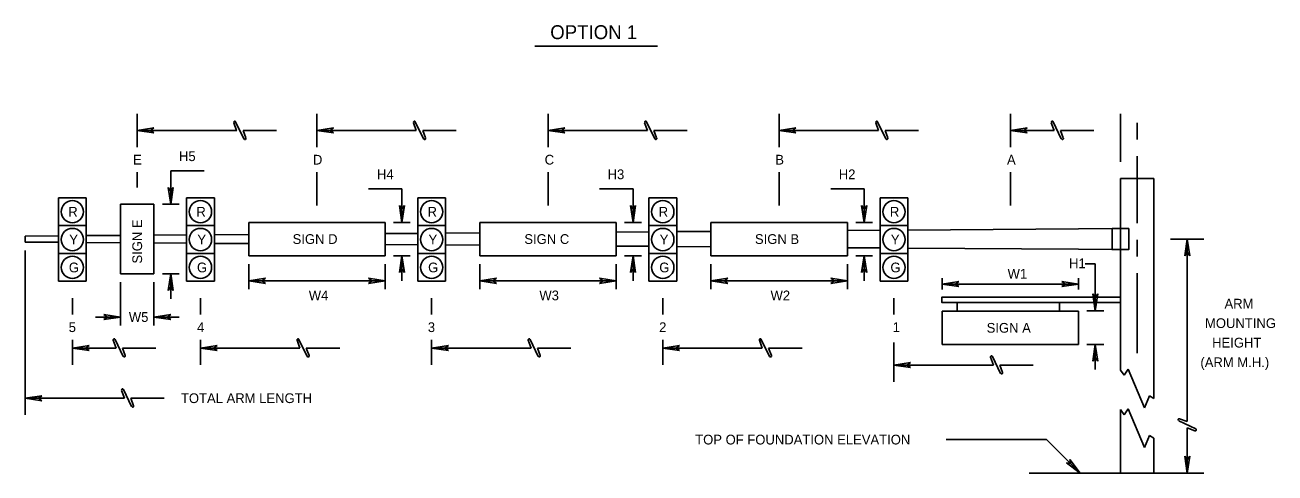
# Model space of a CAD drawing. Extents: x 2146427 to 2147986, y 2147023 to 2147568.
# Drawn here: x 2146426.5 to 2146875.4, y 2147407.4 to 2147568.2 of the extents above; entities that cross this region are included whole.
import ezdxf

# ---------------------------------------------------------------- set-up
doc = ezdxf.new("R2010")
doc.units = 0
doc.layers.add('50', color=7, linetype='Continuous')

msp = doc.modelspace()

# ---------------------------------------------------------------- linework, layer by layer
at = {"layer": '50'}
for p, q in [((2146609.58, 2147560.7), (2146653.58, 2147560.7)), ((2146466.84, 2147524.36), (2146466.84, 2147536.37)), ((2146531.34, 2147524.36), (2146531.34, 2147536.37)), ((2146614.34, 2147524.36), (2146614.34, 2147536.37)), ((2146697.34, 2147524.36), (2146697.34, 2147536.37)), ((2146780.34, 2147524.36), (2146780.34, 2147536.37)), ((2146819.84, 2147519.12), (2146819.84, 2147536.37)), ((2146472.84, 2147531.26), (2146466.84, 2147530.36)), ((2146471.64, 2147530.36), (2146472.84, 2147531.26)), ((2146502.52, 2147530.37), (2146501.52, 2147533.17)), ((2146505.12, 2147527.37), (2146502.17, 2147533.47)), ((2146537.34, 2147531.26), (2146531.34, 2147530.36)), ((2146536.14, 2147530.36), (2146537.34, 2147531.26)), ((2146567.02, 2147530.37), (2146566.02, 2147533.17)), ((2146569.62, 2147527.37), (2146566.67, 2147533.47)), ((2146620.34, 2147531.26), (2146614.34, 2147530.36)), ((2146619.14, 2147530.36), (2146620.34, 2147531.26)), ((2146650.02, 2147530.37), (2146649.02, 2147533.17)), ((2146652.62, 2147527.37), (2146649.67, 2147533.47)), ((2146703.34, 2147531.26), (2146697.34, 2147530.36)), ((2146702.14, 2147530.36), (2146703.34, 2147531.26)), ((2146733.02, 2147530.37), (2146732.02, 2147533.17)), ((2146735.62, 2147527.37), (2146732.67, 2147533.47)), ((2146786.34, 2147531.26), (2146780.34, 2147530.36)), ((2146785.14, 2147530.36), (2146786.34, 2147531.26)), ((2146796.02, 2147530.37), (2146795.02, 2147533.17)), ((2146798.62, 2147527.37), (2146795.67, 2147533.47)), ((2146825.84, 2147527.12), (2146825.84, 2147533.12)), ((2146466.84, 2147530.36), (2146502.54, 2147530.36)), ((2146466.84, 2147530.36), (2146472.84, 2147529.46)), ((2146472.84, 2147529.46), (2146471.64, 2147530.36)), ((2146505.82, 2147527.67), (2146504.82, 2147530.37)), ((2146504.84, 2147530.36), (2146516.84, 2147530.36)), ((2146531.34, 2147530.36), (2146567.04, 2147530.36)), ((2146531.34, 2147530.36), (2146537.34, 2147529.46)), ((2146537.34, 2147529.46), (2146536.14, 2147530.36)), ((2146570.32, 2147527.67), (2146569.32, 2147530.37)), ((2146569.34, 2147530.36), (2146581.34, 2147530.36)), ((2146614.34, 2147530.36), (2146650.04, 2147530.36)), ((2146614.34, 2147530.36), (2146620.34, 2147529.46)), ((2146620.34, 2147529.46), (2146619.14, 2147530.36)), ((2146653.32, 2147527.67), (2146652.32, 2147530.37)), ((2146652.34, 2147530.36), (2146664.34, 2147530.36)), ((2146697.34, 2147530.36), (2146733.04, 2147530.36)), ((2146697.34, 2147530.36), (2146703.34, 2147529.46)), ((2146703.34, 2147529.46), (2146702.14, 2147530.36)), ((2146736.32, 2147527.67), (2146735.32, 2147530.37)), ((2146735.34, 2147530.36), (2146747.34, 2147530.36)), ((2146780.34, 2147530.36), (2146786.34, 2147529.46)), ((2146780.34, 2147530.36), (2146796.04, 2147530.36)), ((2146786.34, 2147529.46), (2146785.14, 2147530.36)), ((2146799.32, 2147527.67), (2146798.32, 2147530.37)), ((2146798.34, 2147530.36), (2146810.34, 2147530.36)), ((2146825.84, 2147521.12), (2146825.84, 2147497.12)), ((2146466.84, 2147509.87), (2146466.84, 2147515.36)), ((2146478.84, 2147503.87), (2146478.84, 2147515.87)), ((2146478.84, 2147515.87), (2146490.84, 2147515.87)), ((2146531.34, 2147503.37), (2146531.34, 2147515.36)), ((2146614.34, 2147503.37), (2146614.34, 2147515.36)), ((2146697.34, 2147503.37), (2146697.34, 2147515.36)), ((2146780.34, 2147503.37), (2146780.34, 2147515.36)), ((2146478.84, 2147508.67), (2146477.94, 2147509.87)), ((2146477.94, 2147509.87), (2146478.84, 2147503.87)), ((2146478.84, 2147503.87), (2146479.74, 2147509.87)), ((2146479.74, 2147509.87), (2146478.84, 2147508.67)), ((2146561.84, 2147509.37), (2146549.84, 2147509.37)), ((2146561.84, 2147497.37), (2146561.84, 2147509.37)), ((2146644.84, 2147509.37), (2146632.84, 2147509.37)), ((2146644.84, 2147497.37), (2146644.84, 2147509.37)), ((2146727.84, 2147509.37), (2146715.84, 2147509.37)), ((2146727.84, 2147497.37), (2146727.84, 2147509.37)), ((2146819.84, 2147513.12), (2146831.84, 2147513.12)), ((2146819.84, 2147513.12), (2146819.84, 2147444.34)), ((2146831.84, 2147513.12), (2146831.84, 2147434.14)), ((2146448.53, 2147506.2), (2146438.53, 2147506.2)), ((2146438.53, 2147506.2), (2146438.53, 2147476.2)), ((2146448.53, 2147506.2), (2146448.53, 2147476.2)), ((2146494.53, 2147506.2), (2146484.53, 2147506.2)), ((2146484.53, 2147506.2), (2146484.53, 2147476.2)), ((2146494.53, 2147506.2), (2146494.53, 2147476.2)), ((2146577.53, 2147506.2), (2146567.53, 2147506.2)), ((2146567.53, 2147506.2), (2146567.53, 2147476.2)), ((2146577.53, 2147506.2), (2146577.53, 2147476.2)), ((2146660.53, 2147506.2), (2146650.53, 2147506.2)), ((2146650.53, 2147506.2), (2146650.53, 2147476.2)), ((2146660.53, 2147506.2), (2146660.53, 2147476.2)), ((2146743.53, 2147506.2), (2146733.53, 2147506.2)), ((2146733.53, 2147506.2), (2146733.53, 2147476.2)), ((2146743.53, 2147506.2), (2146743.53, 2147476.2)), ((2146460.84, 2147503.87), (2146460.84, 2147478.87)), ((2146460.84, 2147503.87), (2146472.84, 2147503.87)), ((2146472.84, 2147503.87), (2146472.84, 2147478.87)), ((2146475.84, 2147503.87), (2146481.84, 2147503.87)), ((2146561.84, 2147502.17), (2146560.94, 2147503.37)), ((2146560.94, 2147503.37), (2146561.84, 2147497.37)), ((2146561.84, 2147497.37), (2146562.74, 2147503.37)), ((2146562.74, 2147503.37), (2146561.84, 2147502.17)), ((2146644.84, 2147502.17), (2146643.94, 2147503.37)), ((2146643.94, 2147503.37), (2146644.84, 2147497.37)), ((2146644.84, 2147497.37), (2146645.74, 2147503.37)), ((2146645.74, 2147503.37), (2146644.84, 2147502.17)), ((2146727.84, 2147502.17), (2146726.94, 2147503.37)), ((2146726.94, 2147503.37), (2146727.84, 2147497.37)), ((2146727.84, 2147497.37), (2146728.74, 2147503.37)), ((2146728.74, 2147503.37), (2146727.84, 2147502.17)), ((2146448.53, 2147496.2), (2146438.53, 2147496.2)), ((2146494.53, 2147496.2), (2146484.53, 2147496.2)), ((2146506.84, 2147497.37), (2146555.84, 2147497.37)), ((2146506.84, 2147497.37), (2146506.84, 2147485.37)), ((2146555.84, 2147497.37), (2146555.84, 2147485.37)), ((2146558.84, 2147497.37), (2146564.84, 2147497.37)), ((2146577.53, 2147496.2), (2146567.53, 2147496.2)), ((2146589.84, 2147497.37), (2146638.84, 2147497.37)), ((2146589.84, 2147497.37), (2146589.84, 2147485.37)), ((2146638.84, 2147497.37), (2146638.84, 2147485.37)), ((2146641.84, 2147497.37), (2146647.84, 2147497.37)), ((2146660.53, 2147496.2), (2146650.53, 2147496.2)), ((2146672.84, 2147497.37), (2146721.84, 2147497.37)), ((2146672.84, 2147497.37), (2146672.84, 2147485.37)), ((2146721.84, 2147497.37), (2146721.84, 2147485.37)), ((2146724.84, 2147497.37), (2146730.84, 2147497.37)), ((2146743.53, 2147496.2), (2146733.53, 2147496.2)), ((2146438.53, 2147492.54), (2146426.53, 2147492.45)), ((2146426.53, 2147490.28), (2146426.53, 2147492.45)), ((2146460.84, 2147492.69), (2146448.53, 2147492.61)), ((2146484.53, 2147492.85), (2146472.84, 2147492.77)), ((2146506.84, 2147493), (2146494.53, 2147492.92)), ((2146567.53, 2147493.42), (2146555.84, 2147493.34)), ((2146589.84, 2147493.57), (2146577.53, 2147493.49)), ((2146650.53, 2147493.98), (2146638.84, 2147493.9)), ((2146672.84, 2147494.14), (2146660.53, 2147494.05)), ((2146733.53, 2147494.55), (2146721.84, 2147494.47)), ((2146804.84, 2147495.04), (2146743.53, 2147494.62)), ((2146816.84, 2147495.12), (2146804.84, 2147495.04)), ((2146825.84, 2147485.12), (2146825.84, 2147491.12)), ((2146837.84, 2147491.37), (2146849.84, 2147491.37)), ((2146843.84, 2147491.37), (2146842.94, 2147485.37)), ((2146844.74, 2147485.37), (2146843.84, 2147491.37)), ((2146843.84, 2147491.37), (2146843.84, 2147425.85)), ((2146438.53, 2147490.2), (2146426.53, 2147490.28)), ((2146426.53, 2147487.28), (2146426.53, 2147428.2)), ((2146460.84, 2147490.05), (2146448.53, 2147490.13)), ((2146484.53, 2147489.89), (2146472.84, 2147489.97)), ((2146506.84, 2147489.74), (2146494.53, 2147489.82)), ((2146567.53, 2147489.32), (2146555.84, 2147489.4)), ((2146589.84, 2147489.17), (2146577.53, 2147489.25)), ((2146650.53, 2147488.76), (2146638.84, 2147488.83)), ((2146672.84, 2147488.6), (2146660.53, 2147488.69)), ((2146733.53, 2147488.19), (2146721.84, 2147488.27)), ((2146804.84, 2147487.7), (2146743.53, 2147488.12)), ((2146816.84, 2147487.62), (2146804.84, 2147487.7)), ((2146842.94, 2147485.37), (2146843.84, 2147486.57)), ((2146843.84, 2147486.57), (2146844.74, 2147485.37)), ((2146448.53, 2147486.2), (2146438.53, 2147486.2)), ((2146494.53, 2147486.2), (2146484.53, 2147486.2)), ((2146506.84, 2147485.37), (2146555.84, 2147485.37)), ((2146506.84, 2147482.37), (2146506.84, 2147473.36)), ((2146555.84, 2147482.37), (2146555.84, 2147473.36)), ((2146558.84, 2147485.37), (2146564.84, 2147485.37)), ((2146561.84, 2147485.37), (2146560.94, 2147479.37)), ((2146561.84, 2147485.37), (2146561.84, 2147476.37)), ((2146562.74, 2147479.37), (2146561.84, 2147485.37)), ((2146577.53, 2147486.2), (2146567.53, 2147486.2)), ((2146589.84, 2147485.37), (2146638.84, 2147485.37)), ((2146589.84, 2147482.37), (2146589.84, 2147473.36)), ((2146638.84, 2147482.37), (2146638.84, 2147473.36)), ((2146641.84, 2147485.37), (2146647.84, 2147485.37)), ((2146644.84, 2147485.37), (2146643.94, 2147479.37)), ((2146644.84, 2147485.37), (2146644.84, 2147476.37)), ((2146645.74, 2147479.37), (2146644.84, 2147485.37)), ((2146660.53, 2147486.2), (2146650.53, 2147486.2)), ((2146672.84, 2147485.37), (2146721.84, 2147485.37)), ((2146672.84, 2147482.37), (2146672.84, 2147473.36)), ((2146721.84, 2147482.37), (2146721.84, 2147473.36)), ((2146724.84, 2147485.37), (2146730.84, 2147485.37)), ((2146727.84, 2147485.37), (2146726.94, 2147479.37)), ((2146727.84, 2147485.37), (2146727.84, 2147476.37)), ((2146728.74, 2147479.37), (2146727.84, 2147485.37)), ((2146743.53, 2147486.2), (2146733.53, 2147486.2)), ((2146810.84, 2147482.46), (2146807.21, 2147482.46)), ((2146810.84, 2147465.65), (2146810.84, 2147482.46)), ((2146460.84, 2147478.87), (2146472.84, 2147478.87)), ((2146475.84, 2147478.87), (2146481.84, 2147478.87)), ((2146478.84, 2147478.87), (2146477.94, 2147472.87)), ((2146478.84, 2147478.87), (2146478.84, 2147469.87)), ((2146479.74, 2147472.87), (2146478.84, 2147478.87)), ((2146560.94, 2147479.37), (2146561.84, 2147480.57)), ((2146561.84, 2147480.57), (2146562.74, 2147479.37)), ((2146643.94, 2147479.37), (2146644.84, 2147480.57)), ((2146644.84, 2147480.57), (2146645.74, 2147479.37)), ((2146726.94, 2147479.37), (2146727.84, 2147480.57)), ((2146727.84, 2147480.57), (2146728.74, 2147479.37)), ((2146825.84, 2147479.12), (2146825.84, 2147450.34)), ((2146438.53, 2147476.2), (2146448.53, 2147476.2)), ((2146460.84, 2147475.87), (2146460.84, 2147460.36)), ((2146472.84, 2147475.87), (2146472.84, 2147460.36)), ((2146477.94, 2147472.87), (2146478.84, 2147474.07)), ((2146478.84, 2147474.07), (2146479.74, 2147472.87)), ((2146484.53, 2147476.2), (2146494.53, 2147476.2)), ((2146506.84, 2147476.37), (2146512.84, 2147477.27)), ((2146506.84, 2147476.37), (2146555.84, 2147476.37)), ((2146512.84, 2147475.47), (2146506.84, 2147476.37)), ((2146512.84, 2147477.27), (2146511.64, 2147476.37)), ((2146511.64, 2147476.37), (2146512.84, 2147475.47)), ((2146555.84, 2147476.37), (2146549.84, 2147477.27)), ((2146549.84, 2147477.27), (2146551.04, 2147476.37)), ((2146551.04, 2147476.37), (2146549.84, 2147475.47)), ((2146549.84, 2147475.47), (2146555.84, 2147476.37)), ((2146567.53, 2147476.2), (2146577.53, 2147476.2)), ((2146589.84, 2147476.37), (2146595.84, 2147477.27)), ((2146589.84, 2147476.37), (2146638.84, 2147476.37)), ((2146595.84, 2147475.47), (2146589.84, 2147476.37)), ((2146595.84, 2147477.27), (2146594.64, 2147476.37)), ((2146594.64, 2147476.37), (2146595.84, 2147475.47)), ((2146638.84, 2147476.37), (2146632.84, 2147477.27)), ((2146632.84, 2147477.27), (2146634.04, 2147476.37)), ((2146634.04, 2147476.37), (2146632.84, 2147475.47)), ((2146632.84, 2147475.47), (2146638.84, 2147476.37)), ((2146650.53, 2147476.2), (2146660.53, 2147476.2)), ((2146672.84, 2147476.37), (2146678.84, 2147477.27)), ((2146672.84, 2147476.37), (2146721.84, 2147476.37)), ((2146678.84, 2147475.47), (2146672.84, 2147476.37)), ((2146678.84, 2147477.27), (2146677.64, 2147476.37)), ((2146677.64, 2147476.37), (2146678.84, 2147475.47)), ((2146721.84, 2147476.37), (2146715.84, 2147477.27)), ((2146715.84, 2147477.27), (2146717.04, 2147476.37)), ((2146717.04, 2147476.37), (2146715.84, 2147475.47)), ((2146715.84, 2147475.47), (2146721.84, 2147476.37)), ((2146733.53, 2147476.2), (2146743.53, 2147476.2)), ((2146755.84, 2147477.37), (2146755.84, 2147473.24)), ((2146755.84, 2147475.18), (2146761.84, 2147476.08)), ((2146755.84, 2147475.18), (2146804.84, 2147475.18)), ((2146761.84, 2147474.28), (2146755.84, 2147475.18)), ((2146761.84, 2147476.08), (2146760.64, 2147475.18)), ((2146760.64, 2147475.18), (2146761.84, 2147474.28)), ((2146804.84, 2147475.18), (2146798.84, 2147476.08)), ((2146798.84, 2147476.08), (2146800.04, 2147475.18)), ((2146800.04, 2147475.18), (2146798.84, 2147474.28)), ((2146798.84, 2147474.28), (2146804.84, 2147475.18)), ((2146804.84, 2147477.37), (2146804.84, 2147473.24)), ((2146443.53, 2147470.2), (2146443.53, 2147464.22)), ((2146489.53, 2147470.2), (2146489.53, 2147464.22)), ((2146572.53, 2147470.2), (2146572.53, 2147464.22)), ((2146655.53, 2147470.2), (2146655.53, 2147464.22)), ((2146738.53, 2147470.2), (2146738.53, 2147464.22)), ((2146761.24, 2147468.62), (2146761.24, 2147465.5)), ((2146798.01, 2147468.62), (2146798.01, 2147465.5)), ((2146810.84, 2147470.45), (2146809.94, 2147471.65)), ((2146809.94, 2147471.65), (2146810.84, 2147465.65)), ((2146810.84, 2147465.65), (2146811.74, 2147471.65)), ((2146811.74, 2147471.65), (2146810.84, 2147470.45)), ((2146460.84, 2147463.37), (2146454.84, 2147464.27)), ((2146454.84, 2147464.27), (2146456.04, 2147463.37)), ((2146472.84, 2147463.37), (2146478.84, 2147464.27)), ((2146478.84, 2147464.27), (2146477.64, 2147463.37)), ((2146755.84, 2147465.5), (2146804.84, 2147465.5)), ((2146755.84, 2147465.5), (2146755.84, 2147453.5)), ((2146804.84, 2147465.5), (2146804.84, 2147453.5)), ((2146807.84, 2147465.65), (2146813.84, 2147465.65)), ((2146451.84, 2147463.37), (2146460.84, 2147463.37)), ((2146456.04, 2147463.37), (2146454.84, 2147462.47)), ((2146454.84, 2147462.47), (2146460.84, 2147463.37)), ((2146478.84, 2147462.47), (2146472.84, 2147463.37)), ((2146481.84, 2147463.37), (2146472.84, 2147463.37)), ((2146477.64, 2147463.37), (2146478.84, 2147462.47)), ((2146443.53, 2147455.22), (2146443.53, 2147446.2)), ((2146459.22, 2147452.22), (2146458.22, 2147455.02)), ((2146461.82, 2147449.22), (2146458.87, 2147455.32)), ((2146489.53, 2147455.22), (2146489.53, 2147446.2)), ((2146525.22, 2147452.22), (2146524.22, 2147455.02)), ((2146527.82, 2147449.22), (2146524.87, 2147455.32)), ((2146572.53, 2147455.22), (2146572.53, 2147446.2)), ((2146608.22, 2147452.22), (2146607.22, 2147455.02)), ((2146610.82, 2147449.22), (2146607.87, 2147455.32)), ((2146655.53, 2147455.22), (2146655.53, 2147446.2)), ((2146691.22, 2147452.22), (2146690.22, 2147455.02)), ((2146693.82, 2147449.22), (2146690.87, 2147455.32)), ((2146443.53, 2147452.22), (2146449.53, 2147453.12)), ((2146443.53, 2147452.22), (2146459.23, 2147452.22)), ((2146449.53, 2147451.32), (2146443.53, 2147452.22)), ((2146449.53, 2147453.12), (2146448.33, 2147452.22)), ((2146448.33, 2147452.22), (2146449.53, 2147451.32)), ((2146462.52, 2147449.52), (2146461.52, 2147452.22)), ((2146461.53, 2147452.22), (2146473.53, 2147452.22)), ((2146489.53, 2147452.22), (2146495.53, 2147453.12)), ((2146489.53, 2147452.22), (2146525.23, 2147452.22)), ((2146495.53, 2147451.32), (2146489.53, 2147452.22)), ((2146495.53, 2147453.12), (2146494.33, 2147452.22)), ((2146494.33, 2147452.22), (2146495.53, 2147451.32)), ((2146528.52, 2147449.52), (2146527.52, 2147452.22)), ((2146527.53, 2147452.22), (2146539.53, 2147452.22)), ((2146572.53, 2147452.22), (2146578.53, 2147453.12)), ((2146572.53, 2147452.22), (2146608.23, 2147452.22)), ((2146578.53, 2147451.32), (2146572.53, 2147452.22)), ((2146578.53, 2147453.12), (2146577.33, 2147452.22)), ((2146577.33, 2147452.22), (2146578.53, 2147451.32)), ((2146611.52, 2147449.52), (2146610.52, 2147452.22)), ((2146610.53, 2147452.22), (2146622.53, 2147452.22)), ((2146655.53, 2147452.22), (2146661.53, 2147453.12)), ((2146655.53, 2147452.22), (2146691.23, 2147452.22)), ((2146661.53, 2147451.32), (2146655.53, 2147452.22)), ((2146661.53, 2147453.12), (2146660.33, 2147452.22)), ((2146660.33, 2147452.22), (2146661.53, 2147451.32)), ((2146694.52, 2147449.52), (2146693.52, 2147452.22)), ((2146693.53, 2147452.22), (2146705.53, 2147452.22)), ((2146738.53, 2147454.18), (2146738.53, 2147440.1)), ((2146755.84, 2147453.5), (2146804.84, 2147453.5)), ((2146807.84, 2147453.5), (2146813.84, 2147453.5)), ((2146810.84, 2147453.5), (2146809.94, 2147447.5)), ((2146810.84, 2147453.5), (2146810.84, 2147444.5)), ((2146811.74, 2147447.5), (2146810.84, 2147453.5)), ((2146738.53, 2147446.11), (2146744.53, 2147447.01)), ((2146738.53, 2147446.11), (2146774.23, 2147446.11)), ((2146744.53, 2147445.21), (2146738.53, 2147446.11)), ((2146744.53, 2147447.01), (2146743.33, 2147446.11)), ((2146743.33, 2147446.11), (2146744.53, 2147445.21)), ((2146774.22, 2147446.11), (2146773.22, 2147448.91)), ((2146776.82, 2147443.11), (2146773.87, 2147449.21)), ((2146777.52, 2147443.41), (2146776.52, 2147446.11)), ((2146776.53, 2147446.11), (2146788.53, 2147446.11)), ((2146809.94, 2147447.5), (2146810.84, 2147448.7)), ((2146810.84, 2147448.7), (2146811.74, 2147447.5)), ((2146819.84, 2147444.34), (2146821.24, 2147442.48)), ((2146821.24, 2147442.48), (2146822.65, 2147444.59)), ((2146822.65, 2147444.59), (2146828.54, 2147430.75)), ((2146462.22, 2147434.22), (2146461.22, 2147437.02)), ((2146464.82, 2147431.22), (2146461.87, 2147437.32)), ((2146426.53, 2147434.22), (2146432.53, 2147435.12)), ((2146432.53, 2147433.32), (2146426.53, 2147434.22)), ((2146426.53, 2147434.22), (2146462.23, 2147434.22)), ((2146432.53, 2147435.12), (2146431.33, 2147434.22)), ((2146431.33, 2147434.22), (2146432.53, 2147433.32)), ((2146465.52, 2147431.52), (2146464.52, 2147434.22)), ((2146464.53, 2147434.22), (2146476.53, 2147434.22)), ((2146828.54, 2147430.75), (2146830.26, 2147435.08)), ((2146830.26, 2147435.08), (2146831.84, 2147434.14)), ((2146819.84, 2147430.11), (2146819.84, 2147407.35)), ((2146819.84, 2147430.11), (2146821.24, 2147428.25)), ((2146821.24, 2147428.25), (2146822.65, 2147430.36)), ((2146822.65, 2147430.36), (2146828.54, 2147416.52)), ((2146840.77, 2147426.15), (2146846.87, 2147423.2)), ((2146841.07, 2147426.85), (2146843.82, 2147425.85)), ((2146843.82, 2147423.55), (2146846.57, 2147422.55)), ((2146843.84, 2147423.55), (2146843.84, 2147407.35)), ((2146793.34, 2147419.35), (2146757.34, 2147419.35)), ((2146805.34, 2147407.35), (2146793.34, 2147419.35)), ((2146828.54, 2147416.52), (2146830.26, 2147420.86)), ((2146830.26, 2147420.86), (2146831.84, 2147419.91)), ((2146831.84, 2147419.91), (2146831.84, 2147407.35)), ((2146801.94, 2147410.75), (2146800.46, 2147410.96)), ((2146800.46, 2147410.96), (2146805.34, 2147407.35)), ((2146805.34, 2147407.35), (2146801.73, 2147412.23)), ((2146801.73, 2147412.23), (2146801.94, 2147410.75)), ((2146843.84, 2147412.15), (2146842.94, 2147413.35)), ((2146842.94, 2147413.35), (2146843.84, 2147407.35)), ((2146843.84, 2147407.35), (2146844.74, 2147413.35)), ((2146844.74, 2147413.35), (2146843.84, 2147412.15)), ((2146787.09, 2147407.35), (2146849.84, 2147407.35))]:
    msp.add_line(p, q, dxfattribs=at)
for points in [[(2146816.84, 2147495.12), (2146816.84, 2147487.62), (2146822.84, 2147487.62), (2146822.84, 2147495.12)], [(2146819.84, 2147470.47), (2146755.71, 2147470.47), (2146755.71, 2147468.62), (2146819.84, 2147468.62)]]:
    msp.add_lwpolyline(points, close=True, dxfattribs=at)
for centre in [(2146443.53, 2147501.2), (2146489.53, 2147501.2), (2146572.53, 2147501.2), (2146655.53, 2147501.2), (2146738.53, 2147501.2), (2146443.53, 2147491.2), (2146489.53, 2147491.2), (2146572.53, 2147491.2), (2146655.53, 2147491.2), (2146738.53, 2147491.2), (2146443.53, 2147481.2), (2146489.53, 2147481.2), (2146572.53, 2147481.2), (2146655.53, 2147481.2), (2146738.53, 2147481.2)]:
    msp.add_circle(centre, 4, dxfattribs=at)
for centre, start, end in [((2146501.88, 2147533.34), 24.9925, 201.4108), ((2146566.38, 2147533.34), 24.9925, 201.4108), ((2146649.38, 2147533.34), 24.9925, 201.4108), ((2146732.38, 2147533.34), 24.9925, 201.4108), ((2146795.39, 2147533.34), 24.9925, 201.4108), ((2146505.51, 2147527.52), 204.9925, 21.4108), ((2146570.01, 2147527.52), 204.9925, 21.4108), ((2146653.01, 2147527.52), 204.9925, 21.4108), ((2146736.01, 2147527.52), 204.9925, 21.4108), ((2146799.01, 2147527.52), 204.9925, 21.4108), ((2146458.58, 2147455.2), 24.9925, 201.4108), ((2146524.58, 2147455.2), 24.9925, 201.4108), ((2146607.58, 2147455.2), 24.9925, 201.4108), ((2146690.58, 2147455.2), 24.9925, 201.4108), ((2146462.2, 2147449.37), 204.9925, 21.4108), ((2146528.2, 2147449.37), 204.9925, 21.4108), ((2146611.2, 2147449.37), 204.9925, 21.4108), ((2146694.2, 2147449.37), 204.9925, 21.4108), ((2146773.58, 2147449.09), 24.9925, 201.4108), ((2146777.2, 2147443.27), 204.9925, 21.4108), ((2146461.58, 2147437.2), 24.9925, 201.4108), ((2146465.2, 2147431.37), 204.9925, 21.4108), ((2146840.91, 2147426.52), 68.5892, 245.0075), ((2146846.73, 2147422.89), 248.5892, 65.0075)]:
    msp.add_arc(centre, 0.37, start, end, dxfattribs=at)

# ---------------------------------------------------------------- texts
for s, height, p in [('OPTION 1', 5, (2146615.12, 2147563.17)), ('H5', 3.5, (2146481.82, 2147519.37)), ('E', 3.5, (2146465.32, 2147518.12)), ('D', 3.5, (2146529.92, 2147518.12)), ('C', 3.5, (2146613.12, 2147518.12)), ('B', 3.5, (2146695.92, 2147518.12)), ('A', 3.5, (2146779.12, 2147518.12)), ('H4', 3.5, (2146552.92, 2147512.87)), ('H3', 3.5, (2146635.72, 2147512.87)), ('H2', 3.5, (2146718.72, 2147512.87)), ('R', 3.5, (2146442.07, 2147499.42)), ('R', 3.5, (2146488.07, 2147499.42)), ('R', 3.5, (2146571.07, 2147499.42)), ('R', 3.5, (2146654.07, 2147499.42)), ('R', 3.5, (2146737.07, 2147499.42)), ('Y', 3.5, (2146442.42, 2147489.42)), ('Y', 3.5, (2146488.42, 2147489.42)), ('SIGN D', 3.5, (2146522.62, 2147489.62)), ('Y', 3.5, (2146571.42, 2147489.42)), ('SIGN C', 3.5, (2146605.82, 2147489.62)), ('Y', 3.5, (2146654.42, 2147489.42)), ('SIGN B', 3.5, (2146688.62, 2147489.62)), ('Y', 3.5, (2146737.42, 2147489.42)), ('G', 3.5, (2146442.27, 2147479.42)), ('G', 3.5, (2146488.27, 2147479.42)), ('G', 3.5, (2146571.27, 2147479.42)), ('G', 3.5, (2146654.27, 2147479.42)), ('G', 3.5, (2146737.27, 2147479.42)), ('H1', 3.5, (2146801.4, 2147480.91)), ('W1', 3.5, (2146779.34, 2147477.17)), ('W3', 3.5, (2146611.22, 2147469.37)), ('W2', 3.5, (2146694.22, 2147469.37)), ('W4', 3.5, (2146528.42, 2147469.37)), ('ARM', 3.5, (2146857.22, 2147466.42)), ('W5', 3.5, (2146463.82, 2147461.62)), ('5', 3.5, (2146442.22, 2147457.97)), ('4', 3.5, (2146488.32, 2147457.97)), ('3', 3.5, (2146571.17, 2147457.97)), ('2', 3.5, (2146654.22, 2147457.97)), ('1', 3.5, (2146738.07, 2147457.97)), ('SIGN A', 3.5, (2146771.82, 2147457.74)), ('MOUNTING', 3.5, (2146850.22, 2147459.42)), ('HEIGHT', 3.5, (2146852.77, 2147452.42)), ('(ARM M.H.)', 3.5, (2146848.57, 2147445.37)), ('TOTAL ARM LENGTH', 3.5001, (2146482.52, 2147432.47)), ('TOP OF FOUNDATION ELEVATION', 3.5001, (2146667.17, 2147417.6))]:
    msp.add_text(s, height=height, dxfattribs=at).set_placement(p)
msp.add_text('SIGN E', height=3.5, rotation=90, dxfattribs=at).set_placement((2146468.57, 2147482.57))

doc.saveas('drawing.dxf')
